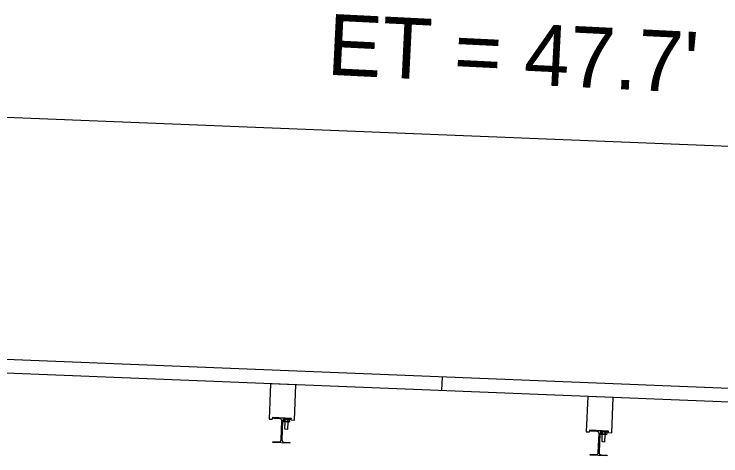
# Model space of a CAD drawing. Extents: x 16537443 to 16538473, y 7054586 to 7055469.
# Drawn here: x 16538413.15 to 16538427.06, y 7055415.07 to 7055423.77 of the extents above; entities that cross this region are included whole.
import ezdxf

# ---------------------------------------------------------------- set-up
doc = ezdxf.new("R2010")
doc.units = 0
doc.layers.add('Draft_DNC', color=7, linetype='Continuous')

msp = doc.modelspace()

# ---------------------------------------------------------------- linework, layer by layer
at = {"layer": 'Draft_DNC'}
for p, q in [((16538399.923, 7055422.26), (16538447.585, 7055420.354)), ((16538437.765, 7055415.974), (16538396.597, 7055417.621)), ((16538437.754, 7055415.704), (16538396.587, 7055417.35)), ((16538421.569, 7055416.351), (16538421.58, 7055416.622)), ((16538418.197, 7055416.486), (16538418.169, 7055415.79)), ((16538418.197, 7055416.486), (16538418.169, 7055415.79)), ((16538418.696, 7055416.466), (16538418.197, 7055416.486)), ((16538418.696, 7055416.466), (16538418.197, 7055416.486)), ((16538418.669, 7055415.77), (16538418.696, 7055416.466)), ((16538418.669, 7055415.77), (16538418.696, 7055416.466)), ((16538424.442, 7055416.236), (16538424.414, 7055415.54)), ((16538424.442, 7055416.236), (16538424.414, 7055415.54)), ((16538424.941, 7055416.216), (16538424.442, 7055416.236)), ((16538424.941, 7055416.216), (16538424.442, 7055416.236)), ((16538424.914, 7055415.52), (16538424.941, 7055416.216)), ((16538424.914, 7055415.52), (16538424.941, 7055416.216)), ((16538418.169, 7055415.79), (16538418.231, 7055415.788)), ((16538418.169, 7055415.79), (16538418.231, 7055415.788)), ((16538418.233, 7055415.819), (16538418.231, 7055415.788)), ((16538418.233, 7055415.819), (16538418.231, 7055415.788)), ((16538418.607, 7055415.804), (16538418.233, 7055415.819)), ((16538418.607, 7055415.804), (16538418.233, 7055415.819)), ((16538418.263, 7055415.802), (16538418.264, 7055415.818)), ((16538418.263, 7055415.802), (16538418.264, 7055415.818)), ((16538418.263, 7055415.802), (16538418.264, 7055415.818)), ((16538418.38, 7055415.797), (16538418.263, 7055415.802)), ((16538418.38, 7055415.797), (16538418.263, 7055415.802)), ((16538418.38, 7055415.797), (16538418.263, 7055415.802)), ((16538418.264, 7055415.818), (16538418.597, 7055415.804)), ((16538418.264, 7055415.818), (16538418.597, 7055415.804)), ((16538418.264, 7055415.818), (16538418.597, 7055415.804)), ((16538418.405, 7055415.379), (16538418.42, 7055415.754)), ((16538418.405, 7055415.379), (16538418.42, 7055415.754)), ((16538418.405, 7055415.379), (16538418.42, 7055415.754)), ((16538418.436, 7055415.754), (16538418.421, 7055415.379)), ((16538418.436, 7055415.754), (16538418.421, 7055415.379)), ((16538418.436, 7055415.754), (16538418.421, 7055415.379)), ((16538418.451, 7055415.748), (16538418.453, 7055415.785)), ((16538418.453, 7055415.785), (16538418.451, 7055415.748)), ((16538418.453, 7055415.785), (16538418.451, 7055415.748)), ((16538418.459, 7055415.742), (16538418.451, 7055415.748)), ((16538418.459, 7055415.742), (16538418.451, 7055415.748)), ((16538418.459, 7055415.742), (16538418.556, 7055415.738)), ((16538418.459, 7055415.742), (16538418.556, 7055415.738)), ((16538418.596, 7055415.789), (16538418.479, 7055415.793)), ((16538418.596, 7055415.789), (16538418.479, 7055415.793)), ((16538418.596, 7055415.789), (16538418.479, 7055415.793)), ((16538418.479, 7055415.59), (16538418.485, 7055415.741)), ((16538418.479, 7055415.59), (16538418.485, 7055415.741)), ((16538418.483, 7055415.788), (16538418.481, 7055415.747)), ((16538418.481, 7055415.747), (16538418.483, 7055415.788)), ((16538418.483, 7055415.788), (16538418.481, 7055415.747)), ((16538418.483, 7055415.788), (16538418.481, 7055415.747)), ((16538418.537, 7055415.739), (16538418.531, 7055415.588)), ((16538418.537, 7055415.739), (16538418.531, 7055415.588)), ((16538418.543, 7055415.786), (16538418.541, 7055415.744)), ((16538418.541, 7055415.744), (16538418.543, 7055415.786)), ((16538418.543, 7055415.786), (16538418.541, 7055415.744)), ((16538418.543, 7055415.786), (16538418.541, 7055415.744)), ((16538418.556, 7055415.738), (16538418.563, 7055415.738)), ((16538418.556, 7055415.738), (16538418.563, 7055415.738)), ((16538418.571, 7055415.743), (16538418.563, 7055415.738)), ((16538418.571, 7055415.743), (16538418.563, 7055415.738)), ((16538418.565, 7055415.79), (16538418.573, 7055415.784)), ((16538418.565, 7055415.79), (16538418.573, 7055415.784)), ((16538418.565, 7055415.79), (16538418.573, 7055415.784)), ((16538418.573, 7055415.784), (16538418.571, 7055415.743)), ((16538418.573, 7055415.784), (16538418.571, 7055415.743)), ((16538418.573, 7055415.784), (16538418.571, 7055415.743)), ((16538418.597, 7055415.804), (16538418.596, 7055415.789)), ((16538418.597, 7055415.804), (16538418.596, 7055415.789)), ((16538418.597, 7055415.804), (16538418.596, 7055415.789)), ((16538418.606, 7055415.773), (16538418.607, 7055415.804)), ((16538418.606, 7055415.773), (16538418.607, 7055415.804)), ((16538418.606, 7055415.773), (16538418.669, 7055415.77)), ((16538418.606, 7055415.773), (16538418.669, 7055415.77)), ((16538418.531, 7055415.588), (16538418.479, 7055415.59)), ((16538418.531, 7055415.588), (16538418.479, 7055415.59)), ((16538424.478, 7055415.569), (16538424.476, 7055415.538)), ((16538424.478, 7055415.569), (16538424.476, 7055415.538)), ((16538424.852, 7055415.554), (16538424.478, 7055415.569)), ((16538424.852, 7055415.554), (16538424.478, 7055415.569)), ((16538424.508, 7055415.552), (16538424.509, 7055415.568)), ((16538424.508, 7055415.552), (16538424.509, 7055415.568)), ((16538424.625, 7055415.548), (16538424.508, 7055415.552)), ((16538424.625, 7055415.548), (16538424.508, 7055415.552)), ((16538424.509, 7055415.568), (16538424.842, 7055415.555)), ((16538424.509, 7055415.568), (16538424.842, 7055415.555)), ((16538424.841, 7055415.539), (16538424.724, 7055415.544)), ((16538424.724, 7055415.544), (16538424.724, 7055415.544)), ((16538424.724, 7055415.544), (16538424.724, 7055415.544)), ((16538424.841, 7055415.539), (16538424.724, 7055415.544)), ((16538424.842, 7055415.555), (16538424.841, 7055415.539)), ((16538424.842, 7055415.555), (16538424.841, 7055415.539)), ((16538424.851, 7055415.523), (16538424.852, 7055415.554)), ((16538424.851, 7055415.523), (16538424.852, 7055415.554)), ((16538424.414, 7055415.54), (16538424.476, 7055415.538)), ((16538424.414, 7055415.54), (16538424.476, 7055415.538)), ((16538424.65, 7055415.13), (16538424.665, 7055415.504)), ((16538424.65, 7055415.13), (16538424.665, 7055415.504)), ((16538424.681, 7055415.504), (16538424.666, 7055415.129)), ((16538424.681, 7055415.504), (16538424.666, 7055415.129)), ((16538424.698, 7055415.535), (16538424.696, 7055415.498)), ((16538424.696, 7055415.498), (16538424.698, 7055415.535)), ((16538424.698, 7055415.535), (16538424.696, 7055415.498)), ((16538424.704, 7055415.492), (16538424.696, 7055415.498)), ((16538424.704, 7055415.492), (16538424.696, 7055415.498)), ((16538424.704, 7055415.492), (16538424.801, 7055415.489)), ((16538424.704, 7055415.492), (16538424.801, 7055415.489)), ((16538424.724, 7055415.34), (16538424.73, 7055415.491)), ((16538424.724, 7055415.34), (16538424.73, 7055415.491)), ((16538424.726, 7055415.497), (16538424.728, 7055415.538)), ((16538424.728, 7055415.538), (16538424.726, 7055415.497)), ((16538424.728, 7055415.538), (16538424.726, 7055415.497)), ((16538424.728, 7055415.538), (16538424.726, 7055415.497)), ((16538424.782, 7055415.489), (16538424.776, 7055415.338)), ((16538424.782, 7055415.489), (16538424.776, 7055415.338)), ((16538424.788, 7055415.536), (16538424.786, 7055415.494)), ((16538424.786, 7055415.494), (16538424.788, 7055415.536)), ((16538424.788, 7055415.536), (16538424.786, 7055415.494)), ((16538424.788, 7055415.536), (16538424.786, 7055415.494)), ((16538424.801, 7055415.489), (16538424.808, 7055415.488)), ((16538424.801, 7055415.489), (16538424.808, 7055415.488)), ((16538424.816, 7055415.493), (16538424.808, 7055415.488)), ((16538424.816, 7055415.493), (16538424.808, 7055415.488)), ((16538424.81, 7055415.54), (16538424.818, 7055415.535)), ((16538424.81, 7055415.54), (16538424.818, 7055415.535)), ((16538424.81, 7055415.54), (16538424.818, 7055415.535)), ((16538424.818, 7055415.535), (16538424.816, 7055415.493)), ((16538424.818, 7055415.535), (16538424.816, 7055415.493)), ((16538424.818, 7055415.535), (16538424.816, 7055415.493)), ((16538424.851, 7055415.523), (16538424.914, 7055415.52)), ((16538424.851, 7055415.523), (16538424.914, 7055415.52)), ((16538418.244, 7055415.329), (16538418.245, 7055415.344)), ((16538418.244, 7055415.329), (16538418.245, 7055415.344)), ((16538418.244, 7055415.329), (16538418.245, 7055415.344)), ((16538418.577, 7055415.315), (16538418.244, 7055415.329)), ((16538418.577, 7055415.315), (16538418.244, 7055415.329)), ((16538418.577, 7055415.315), (16538418.244, 7055415.329)), ((16538418.245, 7055415.344), (16538418.362, 7055415.339)), ((16538418.245, 7055415.344), (16538418.362, 7055415.339)), ((16538418.245, 7055415.344), (16538418.362, 7055415.339)), ((16538418.461, 7055415.336), (16538418.578, 7055415.331)), ((16538418.461, 7055415.336), (16538418.578, 7055415.331)), ((16538418.461, 7055415.336), (16538418.578, 7055415.331)), ((16538418.578, 7055415.331), (16538418.577, 7055415.315)), ((16538418.578, 7055415.331), (16538418.577, 7055415.315)), ((16538418.578, 7055415.331), (16538418.577, 7055415.315)), ((16538424.776, 7055415.338), (16538424.724, 7055415.34)), ((16538424.776, 7055415.338), (16538424.724, 7055415.34)), ((16538424.489, 7055415.079), (16538424.49, 7055415.094)), ((16538424.489, 7055415.079), (16538424.49, 7055415.094)), ((16538424.822, 7055415.065), (16538424.489, 7055415.079)), ((16538424.822, 7055415.065), (16538424.489, 7055415.079)), ((16538424.49, 7055415.094), (16538424.607, 7055415.09)), ((16538424.49, 7055415.094), (16538424.607, 7055415.09)), ((16538424.706, 7055415.086), (16538424.823, 7055415.081)), ((16538424.706, 7055415.086), (16538424.823, 7055415.081)), ((16538424.823, 7055415.081), (16538424.822, 7055415.065)), ((16538424.823, 7055415.081), (16538424.822, 7055415.065))]:
    msp.add_line(p, q, dxfattribs=at)
for points in [[(16538418.571, 7055415.743), (16538418.563, 7055415.738), (16538418.556, 7055415.738), (16538418.459, 7055415.742), (16538418.451, 7055415.748)], [(16538418.453, 7055415.785), (16538418.453, 7055415.785)], [(16538418.479, 7055415.793), (16538418.565, 7055415.79), (16538418.565, 7055415.79)], [(16538424.724, 7055415.544), (16538424.81, 7055415.54), (16538424.81, 7055415.54)], [(16538424.816, 7055415.493), (16538424.808, 7055415.488), (16538424.801, 7055415.489), (16538424.704, 7055415.492), (16538424.696, 7055415.498)], [(16538424.698, 7055415.535), (16538424.698, 7055415.535)]]:
    msp.add_lwpolyline(points, dxfattribs=at)
for points in [[(16538418.537, 7055415.739), (16538418.531, 7055415.588), (16538418.479, 7055415.59), (16538418.485, 7055415.741)], [(16538424.782, 7055415.489), (16538424.776, 7055415.338), (16538424.724, 7055415.34), (16538424.73, 7055415.491)]]:
    msp.add_lwpolyline(points, close=True, dxfattribs=at)
for centre, start, end in [((16538418.379, 7055415.756), 357.7129, 87.7019), ((16538418.379, 7055415.756), 357.7129, 87.7019), ((16538418.379, 7055415.756), 357.7129, 87.7019), ((16538418.478, 7055415.752), 87.7068, 177.7159), ((16538418.478, 7055415.752), 87.7068, 177.7159), ((16538418.478, 7055415.752), 87.7068, 177.7159), ((16538418.478, 7055415.752), 87.7068, 126.8227), ((16538424.624, 7055415.506), 357.7129, 87.7019), ((16538424.624, 7055415.506), 357.7129, 87.7019), ((16538424.723, 7055415.502), 87.7068, 177.7159), ((16538424.723, 7055415.502), 87.7068, 177.7159), ((16538424.723, 7055415.502), 87.7068, 126.8227), ((16538424.723, 7055415.502), 87.7068, 87.7078), ((16538418.364, 7055415.381), 267.7068, 357.7159), ((16538418.364, 7055415.381), 267.7068, 357.7159), ((16538418.364, 7055415.381), 267.7068, 357.7159), ((16538418.463, 7055415.377), 177.7129, 267.7019), ((16538418.463, 7055415.377), 177.7129, 267.7019), ((16538418.463, 7055415.377), 177.7129, 267.7019), ((16538424.609, 7055415.131), 267.7068, 357.7159), ((16538424.609, 7055415.131), 267.7068, 357.7159), ((16538424.708, 7055415.127), 177.7129, 267.7019), ((16538424.708, 7055415.127), 177.7129, 267.7019)]:
    msp.add_arc(centre, 0.0417, start, end, dxfattribs=at)
for points in [[(16538418.481, 7055415.747), (16538418.479, 7055415.745), (16538418.473, 7055415.743), (16538418.465, 7055415.742), (16538418.457, 7055415.744), (16538418.453, 7055415.746), (16538418.451, 7055415.748)], [(16538418.481, 7055415.747), (16538418.479, 7055415.745), (16538418.473, 7055415.743), (16538418.465, 7055415.742), (16538418.457, 7055415.744), (16538418.453, 7055415.746), (16538418.451, 7055415.748)], [(16538418.451, 7055415.748), (16538418.453, 7055415.746), (16538418.457, 7055415.744), (16538418.465, 7055415.742), (16538418.473, 7055415.743), (16538418.479, 7055415.745), (16538418.481, 7055415.747)], [(16538418.481, 7055415.747), (16538418.479, 7055415.745), (16538418.473, 7055415.743), (16538418.465, 7055415.742), (16538418.457, 7055415.744), (16538418.453, 7055415.746), (16538418.451, 7055415.748)], [(16538418.473, 7055415.793), (16538418.474, 7055415.792), (16538418.478, 7055415.792), (16538418.481, 7055415.79), (16538418.483, 7055415.788)], [(16538418.473, 7055415.793), (16538418.474, 7055415.792), (16538418.478, 7055415.792), (16538418.481, 7055415.79), (16538418.483, 7055415.788)], [(16538418.541, 7055415.744), (16538418.536, 7055415.743), (16538418.525, 7055415.74), (16538418.509, 7055415.74), (16538418.495, 7055415.742), (16538418.486, 7055415.745), (16538418.481, 7055415.747)], [(16538418.541, 7055415.744), (16538418.536, 7055415.743), (16538418.525, 7055415.74), (16538418.509, 7055415.74), (16538418.495, 7055415.742), (16538418.486, 7055415.745), (16538418.481, 7055415.747)], [(16538418.481, 7055415.747), (16538418.486, 7055415.745), (16538418.495, 7055415.742), (16538418.509, 7055415.74), (16538418.525, 7055415.74), (16538418.536, 7055415.743), (16538418.541, 7055415.744)], [(16538418.541, 7055415.744), (16538418.536, 7055415.743), (16538418.525, 7055415.74), (16538418.509, 7055415.74), (16538418.495, 7055415.742), (16538418.486, 7055415.745), (16538418.481, 7055415.747)], [(16538418.543, 7055415.786), (16538418.538, 7055415.787), (16538418.529, 7055415.79), (16538418.515, 7055415.792), (16538418.499, 7055415.792), (16538418.488, 7055415.789), (16538418.483, 7055415.788)], [(16538418.483, 7055415.788), (16538418.488, 7055415.789), (16538418.499, 7055415.792), (16538418.515, 7055415.792), (16538418.529, 7055415.79), (16538418.538, 7055415.787), (16538418.543, 7055415.786)], [(16538418.483, 7055415.788), (16538418.488, 7055415.789), (16538418.499, 7055415.792), (16538418.515, 7055415.792), (16538418.529, 7055415.79), (16538418.538, 7055415.787), (16538418.543, 7055415.786)], [(16538418.483, 7055415.788), (16538418.488, 7055415.789), (16538418.499, 7055415.792), (16538418.515, 7055415.792), (16538418.529, 7055415.79), (16538418.538, 7055415.787), (16538418.543, 7055415.786)], [(16538418.571, 7055415.743), (16538418.57, 7055415.742), (16538418.566, 7055415.74), (16538418.56, 7055415.738), (16538418.552, 7055415.738), (16538418.546, 7055415.741), (16538418.542, 7055415.743), (16538418.541, 7055415.744)], [(16538418.571, 7055415.743), (16538418.57, 7055415.742), (16538418.566, 7055415.74), (16538418.56, 7055415.738), (16538418.552, 7055415.738), (16538418.546, 7055415.741), (16538418.542, 7055415.743), (16538418.541, 7055415.744)], [(16538418.541, 7055415.744), (16538418.542, 7055415.743), (16538418.546, 7055415.741), (16538418.552, 7055415.738), (16538418.56, 7055415.738), (16538418.566, 7055415.74), (16538418.57, 7055415.742), (16538418.571, 7055415.743)], [(16538418.571, 7055415.743), (16538418.57, 7055415.742), (16538418.566, 7055415.74), (16538418.56, 7055415.738), (16538418.552, 7055415.738), (16538418.546, 7055415.741), (16538418.542, 7055415.743), (16538418.541, 7055415.744)], [(16538418.573, 7055415.784), (16538418.571, 7055415.786), (16538418.568, 7055415.788), (16538418.562, 7055415.79), (16538418.554, 7055415.79), (16538418.548, 7055415.788), (16538418.544, 7055415.786), (16538418.543, 7055415.786)], [(16538418.543, 7055415.786), (16538418.544, 7055415.786), (16538418.548, 7055415.788), (16538418.554, 7055415.79), (16538418.562, 7055415.79), (16538418.568, 7055415.788), (16538418.571, 7055415.786), (16538418.573, 7055415.784)], [(16538418.543, 7055415.786), (16538418.544, 7055415.786), (16538418.548, 7055415.788), (16538418.554, 7055415.79), (16538418.562, 7055415.79), (16538418.568, 7055415.788), (16538418.571, 7055415.786), (16538418.573, 7055415.784)], [(16538418.543, 7055415.786), (16538418.544, 7055415.786), (16538418.548, 7055415.788), (16538418.554, 7055415.79), (16538418.562, 7055415.79), (16538418.568, 7055415.788), (16538418.571, 7055415.786), (16538418.573, 7055415.784)], [(16538424.718, 7055415.543), (16538424.719, 7055415.543), (16538424.723, 7055415.542), (16538424.726, 7055415.54), (16538424.728, 7055415.538)], [(16538424.718, 7055415.543), (16538424.719, 7055415.543), (16538424.723, 7055415.542), (16538424.726, 7055415.54), (16538424.728, 7055415.538)], [(16538424.728, 7055415.538), (16538424.733, 7055415.54), (16538424.744, 7055415.542), (16538424.76, 7055415.543), (16538424.775, 7055415.54), (16538424.783, 7055415.537), (16538424.788, 7055415.536)], [(16538424.728, 7055415.538), (16538424.733, 7055415.54), (16538424.744, 7055415.542), (16538424.76, 7055415.543), (16538424.775, 7055415.54), (16538424.783, 7055415.537), (16538424.788, 7055415.536)], [(16538424.788, 7055415.536), (16538424.783, 7055415.537), (16538424.775, 7055415.54), (16538424.76, 7055415.543), (16538424.744, 7055415.542), (16538424.733, 7055415.54), (16538424.728, 7055415.538)], [(16538424.728, 7055415.538), (16538424.733, 7055415.54), (16538424.744, 7055415.542), (16538424.76, 7055415.543), (16538424.775, 7055415.54), (16538424.783, 7055415.537), (16538424.788, 7055415.536)], [(16538424.726, 7055415.497), (16538424.724, 7055415.495), (16538424.718, 7055415.493), (16538424.71, 7055415.492), (16538424.702, 7055415.494), (16538424.698, 7055415.497), (16538424.696, 7055415.498)], [(16538424.726, 7055415.497), (16538424.724, 7055415.495), (16538424.718, 7055415.493), (16538424.71, 7055415.492), (16538424.702, 7055415.494), (16538424.698, 7055415.497), (16538424.696, 7055415.498)], [(16538424.696, 7055415.498), (16538424.698, 7055415.497), (16538424.702, 7055415.494), (16538424.71, 7055415.492), (16538424.718, 7055415.493), (16538424.724, 7055415.495), (16538424.726, 7055415.497)], [(16538424.726, 7055415.497), (16538424.724, 7055415.495), (16538424.718, 7055415.493), (16538424.71, 7055415.492), (16538424.702, 7055415.494), (16538424.698, 7055415.497), (16538424.696, 7055415.498)], [(16538424.786, 7055415.494), (16538424.781, 7055415.493), (16538424.77, 7055415.491), (16538424.754, 7055415.49), (16538424.74, 7055415.492), (16538424.731, 7055415.495), (16538424.726, 7055415.497)], [(16538424.786, 7055415.494), (16538424.781, 7055415.493), (16538424.77, 7055415.491), (16538424.754, 7055415.49), (16538424.74, 7055415.492), (16538424.731, 7055415.495), (16538424.726, 7055415.497)], [(16538424.726, 7055415.497), (16538424.731, 7055415.495), (16538424.74, 7055415.492), (16538424.754, 7055415.49), (16538424.77, 7055415.491), (16538424.781, 7055415.493), (16538424.786, 7055415.494)], [(16538424.786, 7055415.494), (16538424.781, 7055415.493), (16538424.77, 7055415.491), (16538424.754, 7055415.49), (16538424.74, 7055415.492), (16538424.731, 7055415.495), (16538424.726, 7055415.497)], [(16538424.816, 7055415.493), (16538424.815, 7055415.492), (16538424.811, 7055415.49), (16538424.805, 7055415.489), (16538424.797, 7055415.489), (16538424.791, 7055415.491), (16538424.787, 7055415.494), (16538424.786, 7055415.494)], [(16538424.816, 7055415.493), (16538424.815, 7055415.492), (16538424.811, 7055415.49), (16538424.805, 7055415.489), (16538424.797, 7055415.489), (16538424.791, 7055415.491), (16538424.787, 7055415.494), (16538424.786, 7055415.494)], [(16538424.786, 7055415.494), (16538424.787, 7055415.494), (16538424.791, 7055415.491), (16538424.797, 7055415.489), (16538424.805, 7055415.489), (16538424.811, 7055415.49), (16538424.815, 7055415.492), (16538424.816, 7055415.493)], [(16538424.816, 7055415.493), (16538424.815, 7055415.492), (16538424.811, 7055415.49), (16538424.805, 7055415.489), (16538424.797, 7055415.489), (16538424.791, 7055415.491), (16538424.787, 7055415.494), (16538424.786, 7055415.494)], [(16538424.788, 7055415.536), (16538424.789, 7055415.537), (16538424.793, 7055415.539), (16538424.799, 7055415.541), (16538424.807, 7055415.54), (16538424.813, 7055415.538), (16538424.816, 7055415.536), (16538424.818, 7055415.535)], [(16538424.788, 7055415.536), (16538424.789, 7055415.537), (16538424.793, 7055415.539), (16538424.799, 7055415.541), (16538424.807, 7055415.54), (16538424.813, 7055415.538), (16538424.816, 7055415.536), (16538424.818, 7055415.535)], [(16538424.818, 7055415.535), (16538424.816, 7055415.536), (16538424.813, 7055415.538), (16538424.807, 7055415.54), (16538424.799, 7055415.541), (16538424.793, 7055415.539), (16538424.789, 7055415.537), (16538424.788, 7055415.536)], [(16538424.788, 7055415.536), (16538424.789, 7055415.537), (16538424.793, 7055415.539), (16538424.799, 7055415.541), (16538424.807, 7055415.54), (16538424.813, 7055415.538), (16538424.816, 7055415.536), (16538424.818, 7055415.535)]]:
    msp.add_open_spline(points, degree=3, dxfattribs=at)

# ---------------------------------------------------------------- texts
msp.add_text("ET = 47.7'", height=1.2, rotation=357.1552, dxfattribs=at).set_placement((16538419.295, 7055422.575))

doc.saveas('drawing.dxf')
